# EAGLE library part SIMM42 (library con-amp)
AMP connector
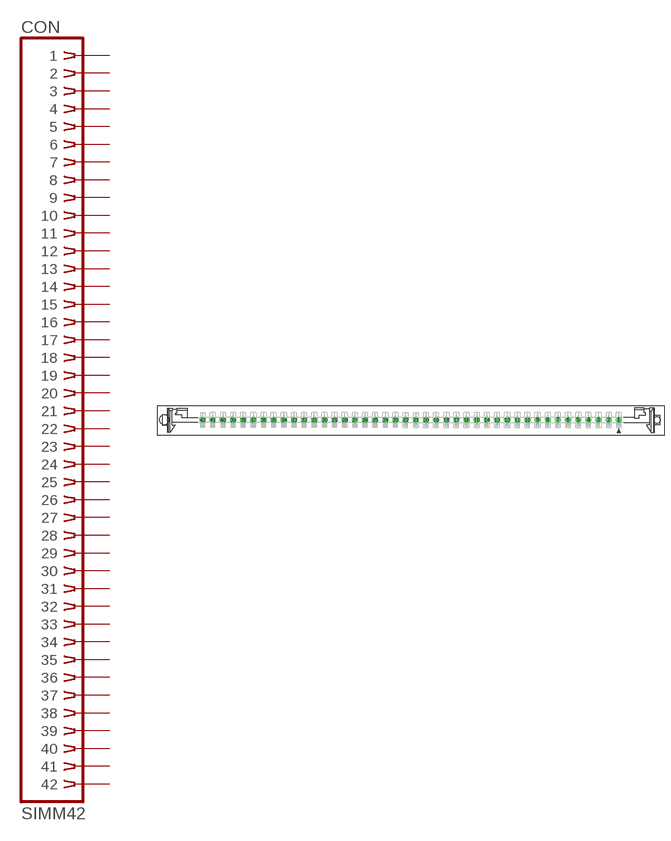
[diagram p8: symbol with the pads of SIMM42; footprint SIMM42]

Designator prefix CON

## SIMM42 (OC_FARNELL: unknown; OC_NEWARK: unknown)  [SIMM42]
1  1  pas
2  2  pas
3  3  pas
4  4  pas
5  5  pas
6  6  pas
7  7  pas
8  8  pas
9  9  pas
10  10  pas
11  11  pas
12  12  pas
13  13  pas
14  14  pas
15  15  pas
16  16  pas
17  17  pas
18  18  pas
19  19  pas
20  20  pas
21  21  pas
22  22  pas
23  23  pas
24  24  pas
25  25  pas
26  26  pas
27  27  pas
28  28  pas
29  29  pas
30  30  pas
31  31  pas
32  32  pas
33  33  pas
34  34  pas
35  35  pas
36  36  pas
37  37  pas
38  38  pas
39  39  pas
40  40  pas
41  41  pas
42  42  pas

## Footprint SIMM42 (pad centres in mm)
SIMM connector
drill 1.016 octagon: 1 52.07,0; 2 49.53,0; 3 46.99,0; 4 44.45,0; 5 41.91,0; 6 39.37,0; 7 36.83,0; 8 34.29,0; 9 31.75,0; 10 29.21,0; 11 26.67,0; 12 24.13,0; 13 21.59,0; 14 19.05,0; 15 16.51,0; 16 13.97,0; 17 11.43,0; 18 8.89,0; 19 6.35,0; 20 3.81,0; 21 1.27,0; 22 -1.27,0; 23 -3.81,0; 24 -6.35,0; 25 -8.89,0; 26 -11.43,0; 27 -13.97,0; 28 -16.51,0; 29 -19.05,0; 30 -21.59,0; 31 -24.13,0; 32 -26.67,0; 33 -29.21,0; 34 -31.75,0; 35 -34.29,0; 36 -36.83,0; 37 -39.37,0; 38 -41.91,0; 39 -44.45,0; 40 -46.99,0; 41 -49.53,0; 42 -52.07,0
hole 2.413 at -61.62,0.025
hole 1.6 at 61.595,0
